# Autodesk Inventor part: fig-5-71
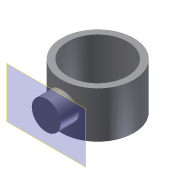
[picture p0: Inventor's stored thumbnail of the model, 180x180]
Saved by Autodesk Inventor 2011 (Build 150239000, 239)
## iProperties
Shininess: 64.0
Length Units: 11269
Angle Units: 11279
Time Units: 11290
Mass Units: 11283
Length Display Precision: 3
Angle Display Precision: 2
Compacted: True
Part Number: fig-5-71
Document SubType Name: Modeling
Created: 2002-12
Designer: deepak
Density: 1 g/cm^3
Density: 0.0
Volumn: 0.0
Area: 0.0
PropertySet Name: Model Information
Control State: 0
Master: False
Checked Out: False
Author: deepak
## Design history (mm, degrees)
sketch "Sketch1"
  geometry: C1 r 23.454 at (0, 0); C2 r 19.43 at (0, 0)
  constraints: 2 centre point, 1 coincident, 1 concentric
extrude "Extrusion1" new body sketch "Sketch1" stored distance "d0" = 30; taper "d1" = 0 deg
workplane "Work Plane1"
workplane "Work Plane2"
sketch "Sketch2"
  geometry: C1 r 9.343 at (0, 0)
  constraints: 1 centre point
extrude "Extrusion2" join sketch "Sketch2" stored distance "d4" = 10; taper "d5" = 0 deg
body "Solid1"
